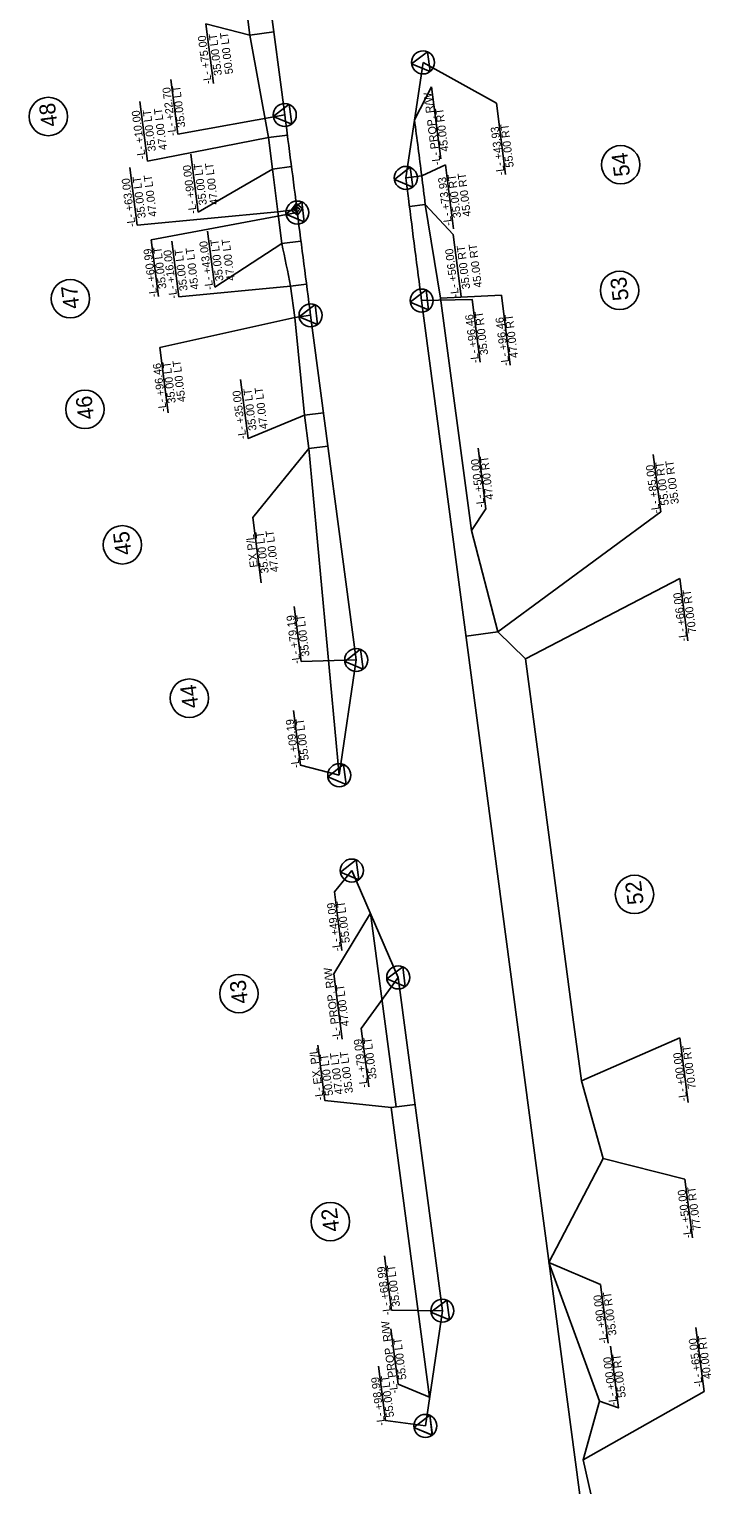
# Model space of a CAD drawing. Extents: x 2368169 to 2369183, y 801414 to 808542.
# Drawn here: x 2368437 to 2368863, y 805179 to 806089 of the extents above; entities that cross this region are included whole.
import ezdxf

# ---------------------------------------------------------------- set-up
doc = ezdxf.new("R2010")
doc.units = 0
for name, color, linetype in [('Prop Easement Construction', 7, 'Continuous'), ('Prop Easement Construction Station Offsets', 7, 'Continuous'), ('Prop Easement Permanent Drainage', 7, 'Continuous'), ('Prop Easement Permanent Drainage Station Offsets', 7, 'Continuous'), ('Prop Easement Permanent Drainage Utility', 7, 'Continuous'), ('Prop Easement Permanent Drainage Utility Station Offsets', 7, 'Continuous'), ('Prop Easement Permanent Utility', 7, 'Continuous'), ('Prop Easement Permanent Utility Station Offsets', 7, 'Continuous'), ('Prop Parcel Number CELL', 7, 'Continuous'), ('Prop Parcel Number Text', 7, 'Continuous'), ('Prop ROW Marker CELL', 7, 'Continuous'), ('Prop ROW Permanent Easement CELL', 7, 'Continuous'), ('Prop ROW RW Lines', 7, 'Continuous'), ('Prop ROW Station Offsets', 7, 'Continuous')]:
    doc.layers.add(name, color=color, linetype=linetype)

msp = doc.modelspace()

# ---------------------------------------------------------------- linework, layer by layer
at = {"layer": 'Prop Easement Construction'}
for p, q in [((2368586.23, 806021.02), (2368574.76, 806085.01)), ((2368693.93, 805920.68), (2368684.34, 805979.2)), ((2368713.15, 805775.48), (2368693.93, 805920.68)), ((2368608.81, 805847.41), (2368602.72, 805908.6)), ((2368630.52, 805622.51), (2368611.55, 805826.65)), ((2368729.61, 805712.1), (2368713.15, 805775.48)), ((2368666.03, 805415.19), (2368650.01, 805536.22)), ((2368793.27, 805231.29), (2368761.63, 805317.89)), ((2368783, 805194.63), (2368793.27, 805231.29)), ((2368799.74, 805121.54), (2368783, 805194.63))]:
    msp.add_line(p, q, dxfattribs=at)
for centre, radius, start, end in [((2358717.33, 804729.9), 10045, 7.246831, 7.448235), ((2360592.8, 804968.88), 8062.36, 7.166068, 7.357029), ((2374854.2, 807222.32), 6386.55, 191.448157, 191.692157)]:
    msp.add_arc(centre, radius, start, end, dxfattribs=at)
at = {"layer": 'Prop Easement Construction Station Offsets'}
for p, q in [((2368688.23, 806052.69), (2368677.57, 806032.04)), ((2368693.97, 806007.73), (2368688.23, 806052.69)), ((2368627.19, 805498.45), (2368650.01, 805536.22)), ((2368632.41, 805457.59), (2368627.19, 805498.45)), ((2368853.48, 805277.46), (2368858.61, 805237.32)), ((2368858.61, 805237.32), (2368783, 805194.63))]:
    msp.add_line(p, q, dxfattribs=at)
for points in [[(2368737.42, 805878.83), (2368731.85, 805922.44), (2368693.93, 805920.68)], [(2368717.3, 805826.88), (2368722.14, 805788.98), (2368713.15, 805775.48)], [(2368800.06, 805265.69), (2368805, 805227.06), (2368793.27, 805231.29)]]:
    msp.add_lwpolyline(points, dxfattribs=at)
at = {"layer": 'Prop Easement Permanent Drainage'}
for p, q in [((2368682.09, 805997.02), (2368672.17, 805995.76)), ((2368684.34, 805979.2), (2368674.42, 805977.94)), ((2368729.61, 805712.1), (2368709.79, 805709.47)), ((2368746.98, 805695.23), (2368729.61, 805712.1)), ((2368761.12, 805588.38), (2368746.98, 805695.23)), ((2368776.62, 805471.36), (2368761.12, 805588.38)), ((2368781.89, 805431.53), (2368776.62, 805471.36)), ((2368795.39, 805382.88), (2368781.89, 805431.53)), ((2368761.63, 805317.89), (2368795.39, 805382.88))]:
    msp.add_line(p, q, dxfattribs=at)
msp.add_arc((2354909.89, 804247.29), 13882.9, 7.166384, 7.240531, dxfattribs=at)
at = {"layer": 'Prop Easement Permanent Drainage Station Offsets'}
for p, q in [((2368682.09, 805997.02), (2368696.85, 806003.93)), ((2368701.95, 805963.94), (2368696.85, 806003.93)), ((2368701.74, 805960.44), (2368684.34, 805979.2)), ((2368706.69, 805921.72), (2368701.74, 805960.44)), ((2368826.81, 805822.91), (2368831.56, 805787.05)), ((2368831.56, 805787.05), (2368729.61, 805712.1)), ((2368843.37, 805745.34), (2368746.98, 805695.23)), ((2368848.51, 805706.48), (2368843.37, 805745.34)), ((2368843.39, 805458.32), (2368781.89, 805431.53)), ((2368848.72, 805418.01), (2368843.39, 805458.32)), ((2368846.44, 805370.03), (2368795.39, 805382.88)), ((2368851.29, 805333.38), (2368846.44, 805370.03)), ((2368793.78, 805304.26), (2368761.63, 805317.89)), ((2368798.63, 805267.6), (2368793.78, 805304.26))]:
    msp.add_line(p, q, dxfattribs=at)
at = {"layer": 'Prop Easement Permanent Drainage Utility'}
for p, q in [((2368574.76, 806085.01), (2368572.14, 806104.84)), ((2368589.63, 806086.97), (2368574.76, 806085.01)), ((2368586.23, 806021.02), (2368598.13, 806022.58)), ((2368588.79, 806001.28), (2368586.23, 806021.02)), ((2368588.79, 806001.28), (2368600.69, 806002.81)), ((2368604.09, 805976.12), (2368592.19, 805974.62)), ((2368594.71, 805954.71), (2368592.19, 805974.62)), ((2368606.61, 805956.23), (2368594.71, 805954.71)), ((2368610.08, 805929.35), (2368600.16, 805928.06)), ((2368602.72, 805908.6), (2368600.16, 805928.06)), ((2368612.64, 805909.91), (2368602.72, 805908.6)), ((2368620.7, 805848.99), (2368608.81, 805847.41)), ((2368611.55, 805826.65), (2368608.81, 805847.41)), ((2368623.45, 805828.21), (2368611.55, 805826.65))]:
    msp.add_line(p, q, dxfattribs=at)
at = {"layer": 'Prop Easement Permanent Drainage Utility Station Offsets'}
for p, q in [((2368547.15, 806091.97), (2368574.76, 806085.01)), ((2368547.15, 806091.97), (2368551.9, 806054.83)), ((2368506.01, 806043.56), (2368510.78, 806006.18)), ((2368510.78, 806006.18), (2368586.23, 806021.02)), ((2368537.79, 806010.59), (2368542.4, 805974.47)), ((2368499.59, 806002.36), (2368504.2, 805966.24)), ((2368542.4, 805974.47), (2368588.79, 806001.28)), ((2368592.19, 805974.62), (2368504.2, 805966.24)), ((2368548.23, 805962.53), (2368552.7, 805927.59)), ((2368525.84, 805956.34), (2368530.3, 805921.41)), ((2368594.71, 805954.71), (2368552.7, 805927.59)), ((2368530.3, 805921.41), (2368600.16, 805928.06)), ((2368518.42, 805889.81), (2368602.72, 805908.6)), ((2368523.64, 805848.95), (2368518.42, 805889.81)), ((2368611.55, 805826.65), (2368576.57, 805783.54)), ((2368581.79, 805742.68), (2368576.57, 805783.54))]:
    msp.add_line(p, q, dxfattribs=at)
msp.add_lwpolyline([(2368568.87, 805869.71), (2368573.56, 805832.97), (2368608.81, 805847.41)], dxfattribs=at)
at = {"layer": 'Prop Easement Permanent Utility'}
for p, q in [((2368663.06, 805414.8), (2368677.93, 805416.75)), ((2368687.02, 805233.86), (2368663.06, 805414.8))]:
    msp.add_line(p, q, dxfattribs=at)
at = {"layer": 'Prop Easement Permanent Utility Station Offsets'}
for points in [[(2368617.17, 805453.85), (2368621.6, 805419.22), (2368663.06, 805414.8)], [(2368662.88, 805276.53), (2368667.3, 805241.9), (2368687.02, 805233.86)]]:
    msp.add_lwpolyline(points, dxfattribs=at)
at = {"layer": 'Prop Parcel Number CELL'}
for p, q in [((2368448.72, 806034.17), (2368448.72, 806034.17)), ((2368806.48, 806004.01), (2368806.48, 806004.01)), ((2368805.74, 805925.48), (2368805.74, 805925.48)), ((2368462.52, 805920.28), (2368462.52, 805920.28)), ((2368471.62, 805851.17), (2368471.62, 805851.17)), ((2368495.01, 805766.49), (2368495.01, 805766.49)), ((2368536.89, 805670.64), (2368536.89, 805670.64)), ((2368815.07, 805547.99), (2368815.07, 805547.99)), ((2368567.86, 805486.04), (2368567.86, 805486.04)), ((2368624.96, 805343.53), (2368624.96, 805343.53))]:
    msp.add_line(p, q, dxfattribs=at)
for centre in [(2368448.72, 806034.17), (2368806.48, 806004.01), (2368805.74, 805925.48), (2368462.52, 805920.28), (2368471.62, 805851.17), (2368495.01, 805766.49), (2368536.89, 805670.64), (2368815.07, 805547.99), (2368567.86, 805486.04), (2368624.96, 805343.53)]:
    msp.add_circle(centre, 12, dxfattribs=at)
at = {"layer": 'Prop ROW Marker CELL'}
for p, q in [((2368682.92, 806067.96), (2368682.92, 806067.96)), ((2368682.92, 806067.96), (2368682.92, 806067.96)), ((2368596.48, 806035.12), (2368596.48, 806035.12)), ((2368596.48, 806035.12), (2368596.48, 806035.12)), ((2368672.17, 805995.76), (2368672.17, 805995.76)), ((2368672.17, 805995.76), (2368672.17, 805995.76)), ((2368604.09, 805976.12), (2368604.09, 805976.12)), ((2368604.34, 805974.14), (2368604.34, 805974.14)), ((2368604.34, 805974.14), (2368604.34, 805974.14)), ((2368682.03, 805919.1), (2368682.03, 805919.1)), ((2368682.03, 805919.1), (2368682.03, 805919.1)), ((2368612.64, 805909.91), (2368612.64, 805909.91)), ((2368612.64, 805909.91), (2368612.64, 805909.91)), ((2368641.15, 805694.52), (2368641.15, 805694.52)), ((2368641.15, 805694.52), (2368641.15, 805694.52)), ((2368630.52, 805622.51), (2368630.52, 805622.51)), ((2368630.52, 805622.51), (2368630.52, 805622.51)), ((2368638.4, 805562.93), (2368638.4, 805562.93)), ((2368638.4, 805562.93), (2368638.4, 805562.93)), ((2368667.42, 805496.15), (2368667.42, 805496.15)), ((2368667.42, 805496.15), (2368667.42, 805496.15)), ((2368695, 805287.87), (2368695, 805287.87)), ((2368695, 805287.87), (2368695, 805287.87)), ((2368684.36, 805215.86), (2368684.36, 805215.86)), ((2368684.36, 805215.86), (2368684.36, 805215.86))]:
    msp.add_line(p, q, dxfattribs=at)
for points in [[(2368687.29, 806062.22), (2368675.78, 806067.04), (2368685.69, 806074.62)], [(2368687.28, 806062.22), (2368675.78, 806067.05), (2368685.7, 806074.62)], [(2368600.84, 806029.38), (2368589.33, 806034.21), (2368599.26, 806041.78)], [(2368600.85, 806029.39), (2368589.34, 806034.2), (2368599.25, 806041.78)], [(2368676.53, 805990.02), (2368665.02, 805994.84), (2368674.94, 806002.42)], [(2368676.53, 805990.02), (2368665.02, 805994.85), (2368674.94, 806002.41)], [(2368608.71, 805968.4), (2368597.2, 805973.21), (2368607.11, 805980.79)], [(2368608.71, 805968.39), (2368597.2, 805973.22), (2368607.12, 805980.79)], [(2368686.4, 805913.36), (2368674.89, 805918.18), (2368684.8, 805925.76)], [(2368686.39, 805913.36), (2368674.89, 805918.19), (2368684.81, 805925.76)], [(2368617, 805904.17), (2368605.49, 805908.99), (2368615.41, 805916.57)], [(2368617, 805904.17), (2368605.49, 805909), (2368615.41, 805916.57)], [(2368645.52, 805688.78), (2368634.01, 805693.6), (2368643.93, 805701.18)], [(2368645.52, 805688.78), (2368634.01, 805693.61), (2368643.93, 805701.18)], [(2368634.88, 805616.77), (2368623.37, 805621.59), (2368633.29, 805629.16)], [(2368634.88, 805616.76), (2368623.37, 805621.59), (2368633.29, 805629.16)], [(2368642.77, 805557.19), (2368631.26, 805562.01), (2368641.18, 805569.59)], [(2368642.77, 805557.18), (2368631.26, 805562.02), (2368641.18, 805569.58)], [(2368671.79, 805490.42), (2368660.28, 805495.23), (2368670.19, 805502.81)], [(2368671.78, 805490.41), (2368660.28, 805495.24), (2368670.2, 805502.81)], [(2368699.37, 805282.13), (2368687.86, 805286.95), (2368697.77, 805294.53)], [(2368699.36, 805282.13), (2368687.86, 805286.96), (2368697.78, 805294.53)], [(2368688.73, 805210.12), (2368677.22, 805214.94), (2368687.13, 805222.52)], [(2368688.72, 805210.11), (2368677.22, 805214.95), (2368687.14, 805222.51)]]:
    msp.add_lwpolyline(points, close=True, dxfattribs=at)
for centre in [(2368682.92, 806067.96), (2368596.48, 806035.12), (2368672.17, 805995.76), (2368604.34, 805974.14), (2368682.03, 805919.1), (2368612.64, 805909.91), (2368641.15, 805694.52), (2368630.52, 805622.51), (2368638.4, 805562.93), (2368667.42, 805496.15), (2368695, 805287.87), (2368684.36, 805215.86)]:
    msp.add_circle(centre, 7.2, dxfattribs=at)
at = {"layer": 'Prop ROW Permanent Easement CELL'}
for points in [[(2368600.52, 805975.68), (2368603.65, 805979.7), (2368607.66, 805976.57), (2368604.54, 805972.55)], [(2368602.31, 805975.9), (2368603.87, 805977.91), (2368605.88, 805976.35), (2368604.32, 805974.34)]]:
    msp.add_lwpolyline(points, close=True, dxfattribs=at)
at = {"layer": 'Prop ROW RW Lines'}
for p, q in [((2368596.48, 806035.12), (2368546.8, 806411.1)), ((2368682.92, 806067.96), (2368672.17, 805995.76)), ((2368787.84, 805119.96), (2368682.03, 805919.1)), ((2368641.15, 805694.52), (2368612.64, 805909.91)), ((2368630.52, 805622.51), (2368641.15, 805694.52)), ((2368667.42, 805496.15), (2368638.4, 805562.93)), ((2368695, 805287.87), (2368667.42, 805496.15)), ((2368684.36, 805215.86), (2368695, 805287.87))]:
    msp.add_line(p, q, dxfattribs=at)
for centre, radius, start, end in [((2358717.33, 804729.9), 9965, 7.172685, 7.526261), ((2358717.33, 804729.9), 10035, 7.172685, 7.246831), ((2378560.81, 807227.11), 9965, 187.172674, 187.5424), ((2378560.81, 807227.11), 10035, 187.172674, 187.5424)]:
    msp.add_arc(centre, radius, start, end, dxfattribs=at)
at = {"layer": 'Prop ROW Station Offsets'}
for p, q in [((2368525.23, 806057.27), (2368529.6, 806023.04)), ((2368529.6, 806023.04), (2368596.48, 806035.12)), ((2368513.02, 805957.05), (2368604.34, 805974.14)), ((2368517.54, 805921.72), (2368513.02, 805957.05))]:
    msp.add_line(p, q, dxfattribs=at)
for points in [[(2368734.54, 805997.95), (2368728.86, 806042.42), (2368682.92, 806067.96)], [(2368718.56, 805880.64), (2368713.55, 805919.86), (2368682.03, 805919.1)], [(2368602.39, 805727.96), (2368606.77, 805693.66), (2368641.15, 805694.52)], [(2368601.92, 805663), (2368606.29, 805628.84), (2368630.52, 805622.51)], [(2368632.22, 805512.99), (2368627.54, 805549.64), (2368638.4, 805562.93)], [(2368648.94, 805427.78), (2368644.29, 805464.17), (2368667.42, 805496.15)], [(2368658.9, 805322.2), (2368663.23, 805288.26), (2368695, 805287.87)], [(2368655.13, 805253.1), (2368659.47, 805219.17), (2368684.36, 805215.86)]]:
    msp.add_lwpolyline(points, dxfattribs=at)

# ---------------------------------------------------------------- texts
at = {"layer": 'Prop Easement Construction Station Offsets'}
for s, p in [('-L- PROP. R/W', (2368693.93, 806004.1)), ('45.00 RT', (2368698.92, 806012.45)), ('-L- +96.46', (2368736.94, 805878.59)), ('47.00 RT', (2368742.36, 805883.54)), ('-L- +50.00', (2368721.51, 805790.02)), ('47.00 RT', (2368726.92, 805794.99)), ('-L- PROP. R/W', (2368631.53, 805457.22)), ('47.00 LT', (2368636.72, 805465.9)), ('-L- +65.00', (2368857.7, 805240.5)), ('40.00 RT', (2368863.11, 805245.47)), ('55.00 RT', (2368809.68, 805233.8)), ('-L- +00.00', (2368804.26, 805228.84))]:
    msp.add_text(s, height=5, rotation=97.27835, dxfattribs=at).set_placement(p)
at = {"layer": 'Prop Easement Permanent Drainage Station Offsets'}
for s, rotation, p in [('35.00 RT', 97.27835, (2368706.71, 805971.08)), ('45.00 RT', 97.27835, (2368712.91, 805971.87)), ('-L- +73.93', 97.27835, (2368701.04, 805966.18)), ('-L- +56.00', 97.27835, (2368705.46, 805921.42)), ('35.00 RT', 97.27835, (2368712.37, 805926.58)), ('45.00 RT', 97.27835, (2368719.81, 805927.53)), ('-L- +85.00', 97.54241, (2368831.02, 805786.39)), ('55.00 RT', 97.54241, (2368836.65, 805791.42)), ('35.00 RT', 97.54241, (2368842.85, 805792.24)), ('-L- +66.00', 97.54241, (2368848.14, 805706.5)), ('70.00 RT', 97.54241, (2368853.77, 805711.53)), ('70.00 RT', 97.54241, (2368853.5, 805426.71)), ('-L- +00.00', 97.54241, (2368848.11, 805419.1)), ('-L- +50.00', 97.54241, (2368850.92, 805333.39)), ('77.00 RT', 97.54241, (2368856.56, 805338.42)), ('-L- +90.00', 97.54241, (2368798.25, 805267.62)), ('35.00 RT', 97.54241, (2368803.89, 805272.65))]:
    msp.add_text(s, height=5, rotation=rotation, dxfattribs=at).set_placement(p)
at = {"layer": 'Prop Easement Permanent Drainage Utility Station Offsets'}
for s, p in [('-L- +75.00', (2368550.91, 806054.66)), ('35.00 LT', (2368557.28, 806060.05)), ('50.00 LT', (2368564.22, 806060.93)), ('-L- +10.00', (2368509.56, 806007.83)), ('35.00 LT', (2368516.01, 806012.62)), ('47.00 LT', (2368522.95, 806013.51)), ('47.00 LT', (2368516.61, 805971.72)), ('-L- +90.00', (2368541.5, 805973.68)), ('35.00 LT', (2368547.87, 805979.07)), (' 47.00 LT', (2368555.13, 805977.47)), ('-L- +63.00', (2368503.29, 805965.45)), ('35.00 LT', (2368509.66, 805970.83)), ('45.00 LT', (2368542.78, 805926.29)), ('-L- +43.00', (2368551.86, 805926.2)), ('35.00 LT', (2368558.23, 805931.59)), (' 47.00 LT', (2368565.49, 805930)), ('-L- +16.00', (2368529.4, 805920.61)), ('35.00 LT', (2368535.84, 805925.41)), ('-L- +96.46', (2368522.75, 805849.89)), ('35.00 LT', (2368528.38, 805855.17)), ('45.00 LT', (2368534.58, 805855.96)), ('-L- +35.00', (2368572.57, 805832.79)), ('35.00 LT', (2368578.94, 805838.18)), ('47.00 LT', (2368585.88, 805839.07)), ('EX P/L', (2368579.75, 805752.61)), ('35.00 LT', (2368586.52, 805748.9)), ('47.00 LT', (2368592.72, 805749.69))]:
    msp.add_text(s, height=5, rotation=97.27835, dxfattribs=at).set_placement(p)
at = {"layer": 'Prop Easement Permanent Utility Station Offsets'}
for s, p in [('-L- EX. P/L', (2368620.84, 805419.68)), ('50.00 LT', (2368626.78, 805422.47)), ('47.00 LT', (2368632.98, 805423.26)), ('35.00 LT', (2368639.18, 805424.05)), ('-L- PROP. R/W', (2368667.38, 805236.34)), ('55.00 LT', (2368672.57, 805245.02))]:
    msp.add_text(s, height=5, rotation=97.27835, dxfattribs=at).set_placement(p)
at = {"layer": 'Prop Parcel Number Text'}
for s, p in [('48', (2368454.56, 806028.37)), ('54', (2368812.38, 805997.28)), ('53', (2368811.58, 805919.67)), ('47', (2368468.37, 805914.44)), ('46', (2368477.47, 805845.39)), ('45', (2368500.86, 805760.67)), ('44', (2368542.73, 805664.88)), ('52', (2368820.91, 805542.25)), ('43', (2368573.7, 805480.28)), ('42', (2368630.8, 805337.77))]:
    msp.add_text(s, height=10, rotation=97.27835, dxfattribs=at).set_placement(p)
at = {"layer": 'Prop ROW Station Offsets'}
for s, p in [('-L- +22.70', (2368528.76, 806022.29)), ('35.00 LT', (2368534.38, 806027.58)), ('-L- +43.93', (2368733.94, 805997.72)), ('55.00 RT', (2368739.62, 806002.61)), ('-L- +60.99', (2368516.94, 805921.47)), ('35.00 LT', (2368522.57, 805926.73)), ('-L- +96.46', (2368717.96, 805880.38)), ('35.00 RT', (2368723.62, 805885.37)), ('-L- +79.19', (2368606.3, 805692.38)), ('35.00 LT', (2368612.01, 805697.04)), ('-L- +09.19', (2368605.84, 805627.42)), ('55.00 LT', (2368611.54, 805632.08)), ('-L- +49.09', (2368631.62, 805512.74)), ('55.00 LT', (2368637.25, 805517.99)), ('-L- +79.09', (2368648.34, 805427.54)), ('35.00 LT', (2368653.97, 805432.79)), ('-L- +68.99', (2368662.97, 805285.37)), ('35.00 LT', (2368668.6, 805290.62)), ('-L- +98.99', (2368659.21, 805216.28)), ('55.00 LT', (2368664.84, 805221.53))]:
    msp.add_text(s, height=5, rotation=97.27835, dxfattribs=at).set_placement(p)

doc.saveas('drawing.dxf')
